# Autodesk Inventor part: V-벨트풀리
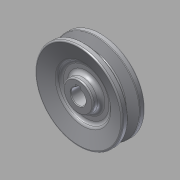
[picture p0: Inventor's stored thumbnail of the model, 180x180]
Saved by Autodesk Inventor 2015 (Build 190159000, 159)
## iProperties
Created: 2016-08
Part Number: V-벨트풀리
Material: 알루미늄 6061
Document SubType Name: Modeling
Designer: mduedu
Density: 2.71 g/cm^3
Appearance: 알루미늄 - 평지
Author: mduedu
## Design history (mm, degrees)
sketch "스케치1"
  geometry: L1 (0, 9.5)-(0, -9.5); L2 (0, 9.5)-(35, 9.5); L3 (35, 9.5)-(35, 4.825); L4 (35, 4.825)-(26, 2.074); L5 (26, 2.074)-(26, 0); L6 (0, 0)-(26, 0); L7 (0, -9.5)-(35, -9.5); L8 (35, -9.5)-(35, -4.825); L9 (35, -4.825)-(26, -2.074); L10 (26, -2.074)-(26, 0); L11 (32.3, 9.5)-(32.3, -9.5); 3 further points
  constraints: 22 end point, 6 point on line, 4 perpendicular, 3 symmetric about line, 1 coincident, 1 horizontal alignment, 1 midpoint, 1 parallel, 1 vertical
  dimensions: "d0" = 19 distance of L1.start L1.end; "d2" = 70 diameter of L8 L1; "d4" = 6.3 distance between parallel lines of L10 L11; "d5" = 2.7 distance between parallel lines of L11 L8; "d6" = 8 distance of point (32.3, -4) point (32.3, 4); "d7" = 34 deg angle of L9 L4
revolve "회전1" sketch "스케치1" stored, may be unused: angle "d8" = 90 deg
sketch "스케치2"
  geometry: L1 (-2, 0)-(2, 0); L2 (2, 0)-(2, 7.8); L3 (2, 7.8)-(-2, 7.8); L4 (-2, 7.8)-(-2, 0); C1 r 6 at (0, 0); 2 further points
  constraints: 8 end point, 2 coincident, 2 parallel, 1 centre point, 1 horizontal, 1 midpoint, 1 perpendicular
  dimensions: "d9" = 12 diameter of C1; "d11" = 4 distance of L2.end L3.end; "d12" = 7.8 distance of L1.end L2.end
extrude "돌출1" cut sketch "스케치2" stored distance "d13" = 10; taper "d14" = 0 deg
sketch "스케치3"
  geometry: L1 (35, 4.825)-(26, 2.074) reference; L2 (26, 2.074)-(26, -2.074) reference; L3 (0, 0)-(26, 0); L4 (35, 9.5)-(35, 4.825) reference; L5 (-35, 9.5)-(35, 9.5) reference; L6 (35, 9.5)-(21, 5.22); L7 (21, 5.22)-(21, 3); L8 (21, 3)-(12, 3); L9 (12, 3)-(12, 9.5); L10 (0, 9.5)-(0, -9.5); L11 (5.657, -9.5)-(-6, -9.5) reference; L12 (12, 9.5)-(35, 9.5)
  constraints: 14 end point, 3 midpoint, 2 parallel, 2 perpendicular, 2 point on line, 1 collinear, 1 horizontal
  dimensions: "d15" = 3 distance between parallel lines of L3 L8; "d17" = 42 diameter of L7 L10; "d18" = 24 diameter of L9 L10
revolve "회전2" sketch "스케치3" stored, may be unused: angle "d19" = 90 deg
fillet "모깎기1" dims "d20" = 0.5, "d21" = 1, "d22" = 1
fillet "모깎기2" dims "d23" = 3
fillet "모깎기3" dims "d24" = 3
fillet "모깎기4" dims "d25" = 3
chamfer "모따기1" distance "d26" = 0.5; stored, may be unused: second distance "d27" = 2, angle "d28" = 45 deg
fillet "모깎기5" dims "d29" = 1
node "솔리드1"
mirror "대칭1"
